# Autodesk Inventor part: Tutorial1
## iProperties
Created: 2009-03
Part Number: Tutorial1
Document SubType Name: Modeling
Designer: Sham
Density: 1 g/cm^3
Author: Sham
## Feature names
1. Extrusion1
2. Extrusion2
3. Extrusion3
4. Fillet1
5. Hole1
6. Hole2
